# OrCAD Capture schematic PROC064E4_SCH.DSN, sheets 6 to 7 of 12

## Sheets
6 07. RGMII ETHERNET PHY 1: size C; title: RGMII ETHERNET PHY 1
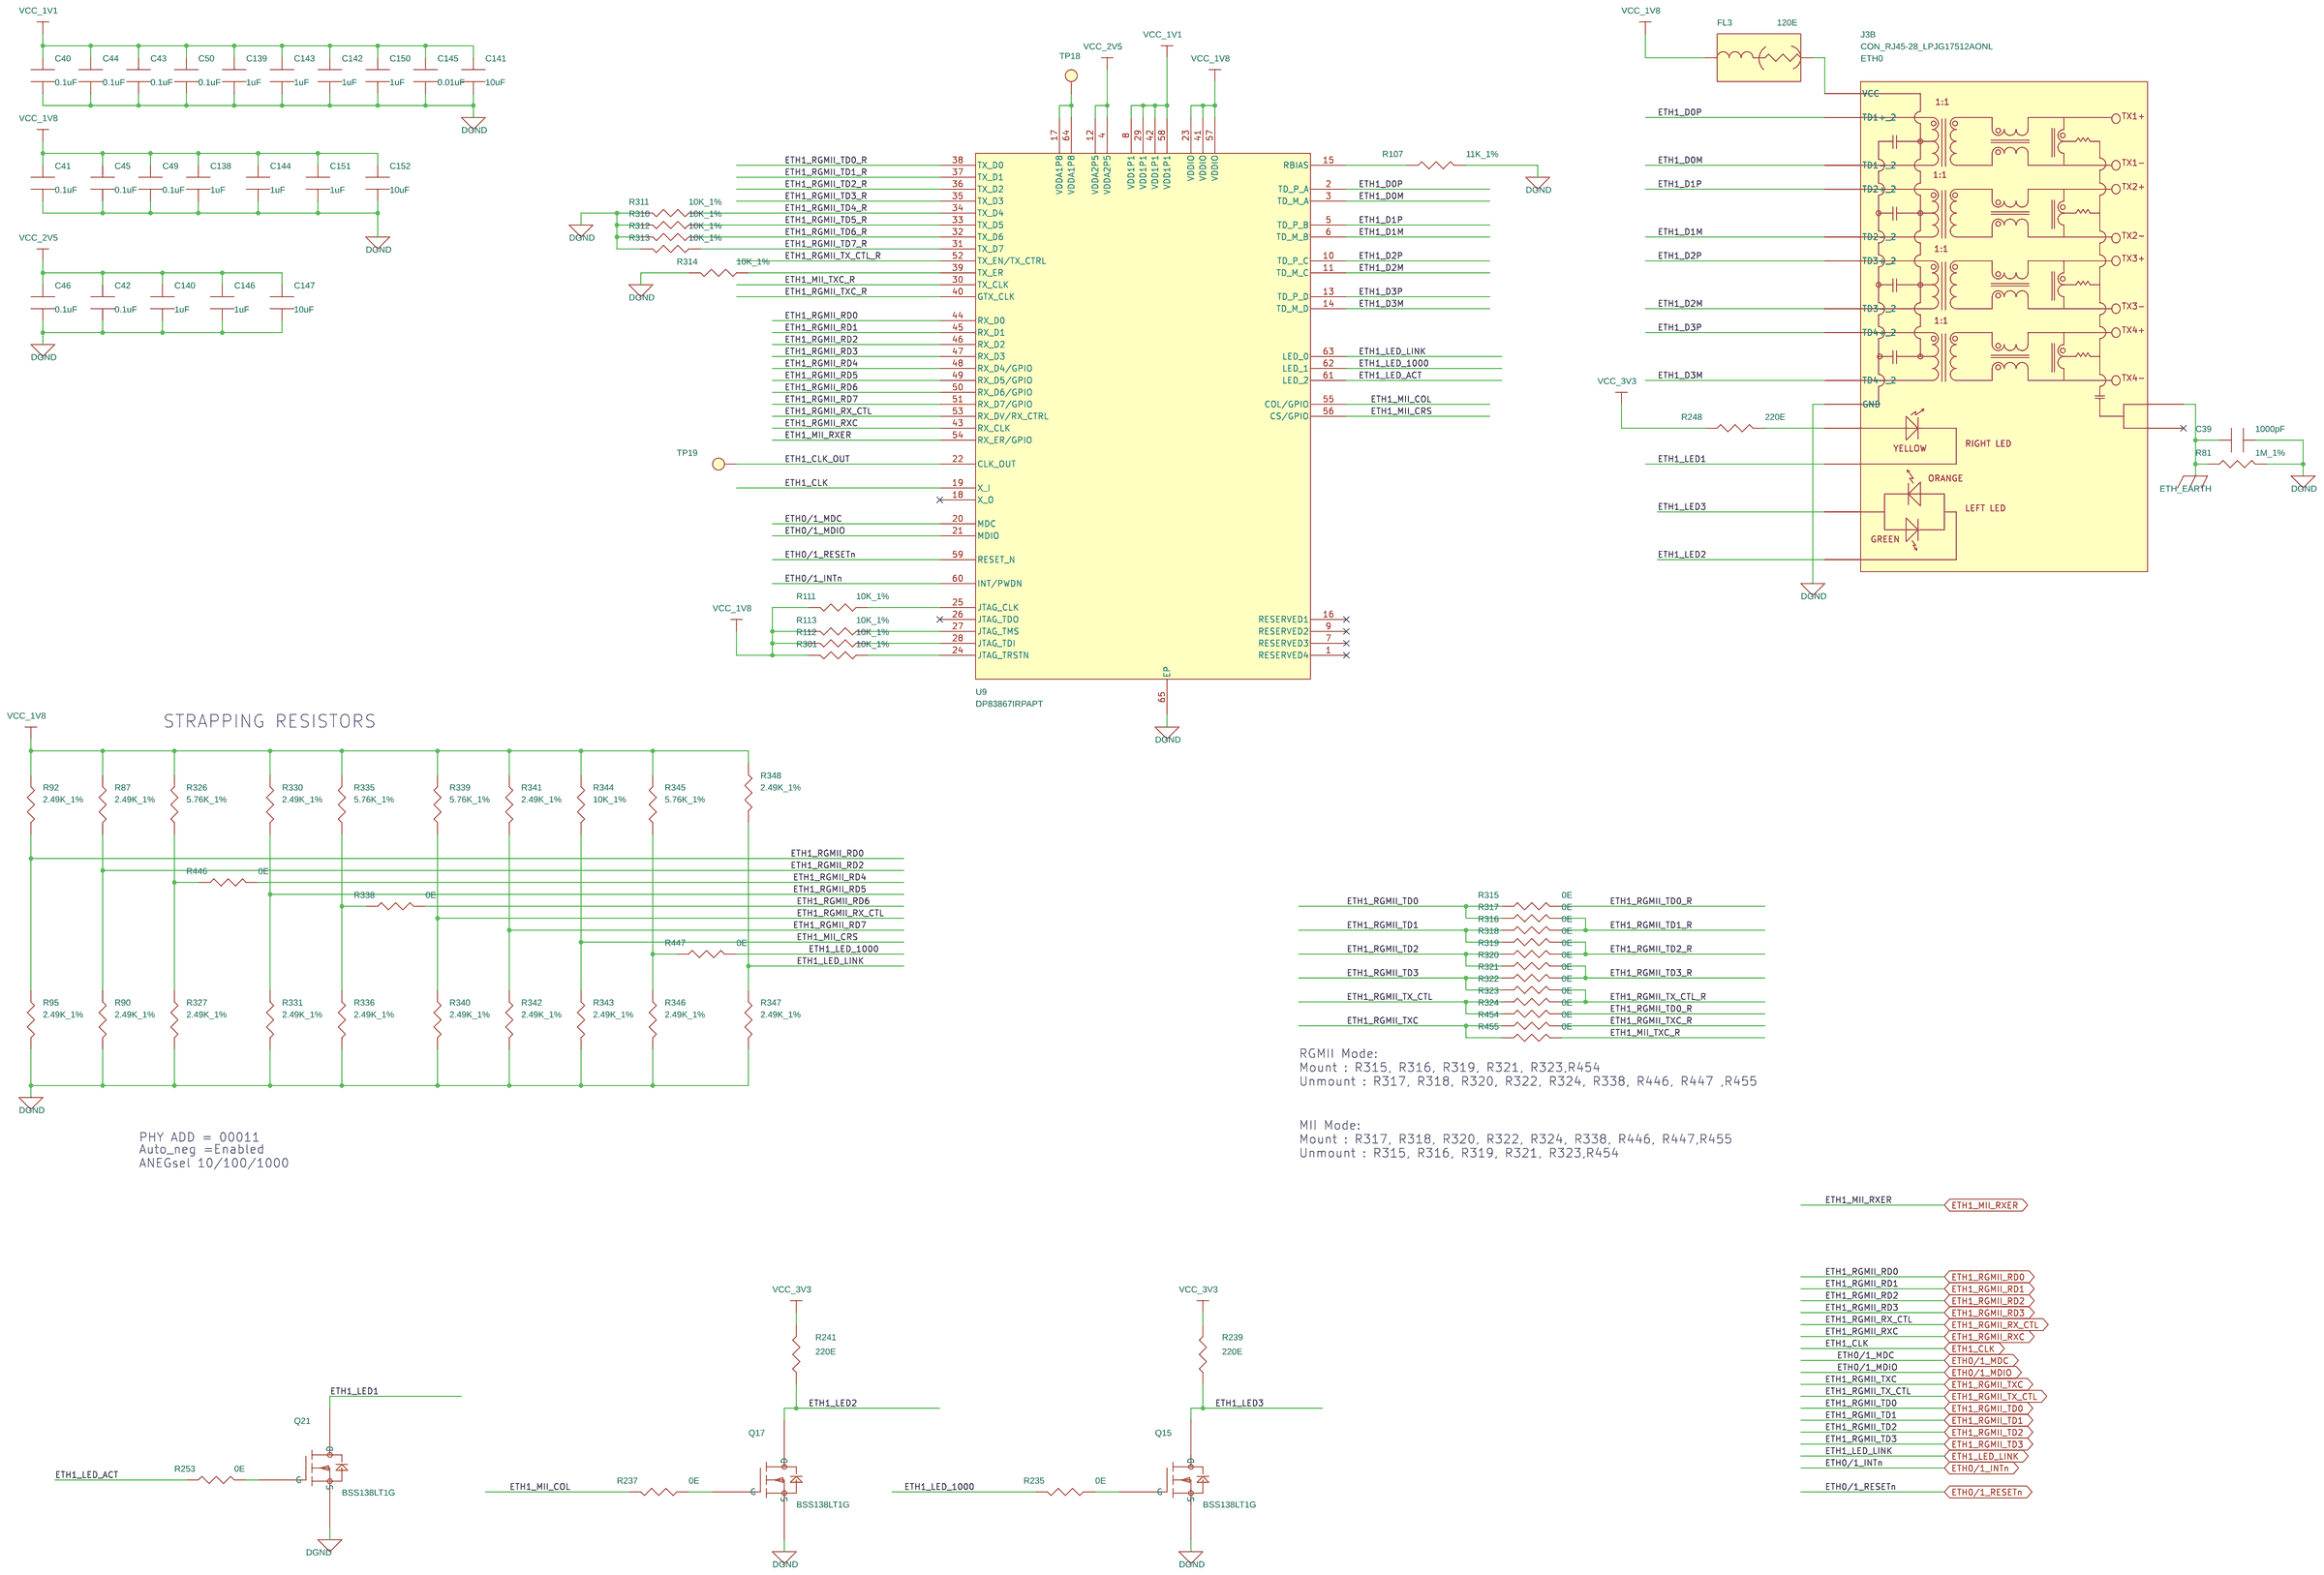
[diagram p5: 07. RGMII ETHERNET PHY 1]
7 08. RGMII ETHERNET PHY 2: size C; title: RGMII ETHERNET PHY 2
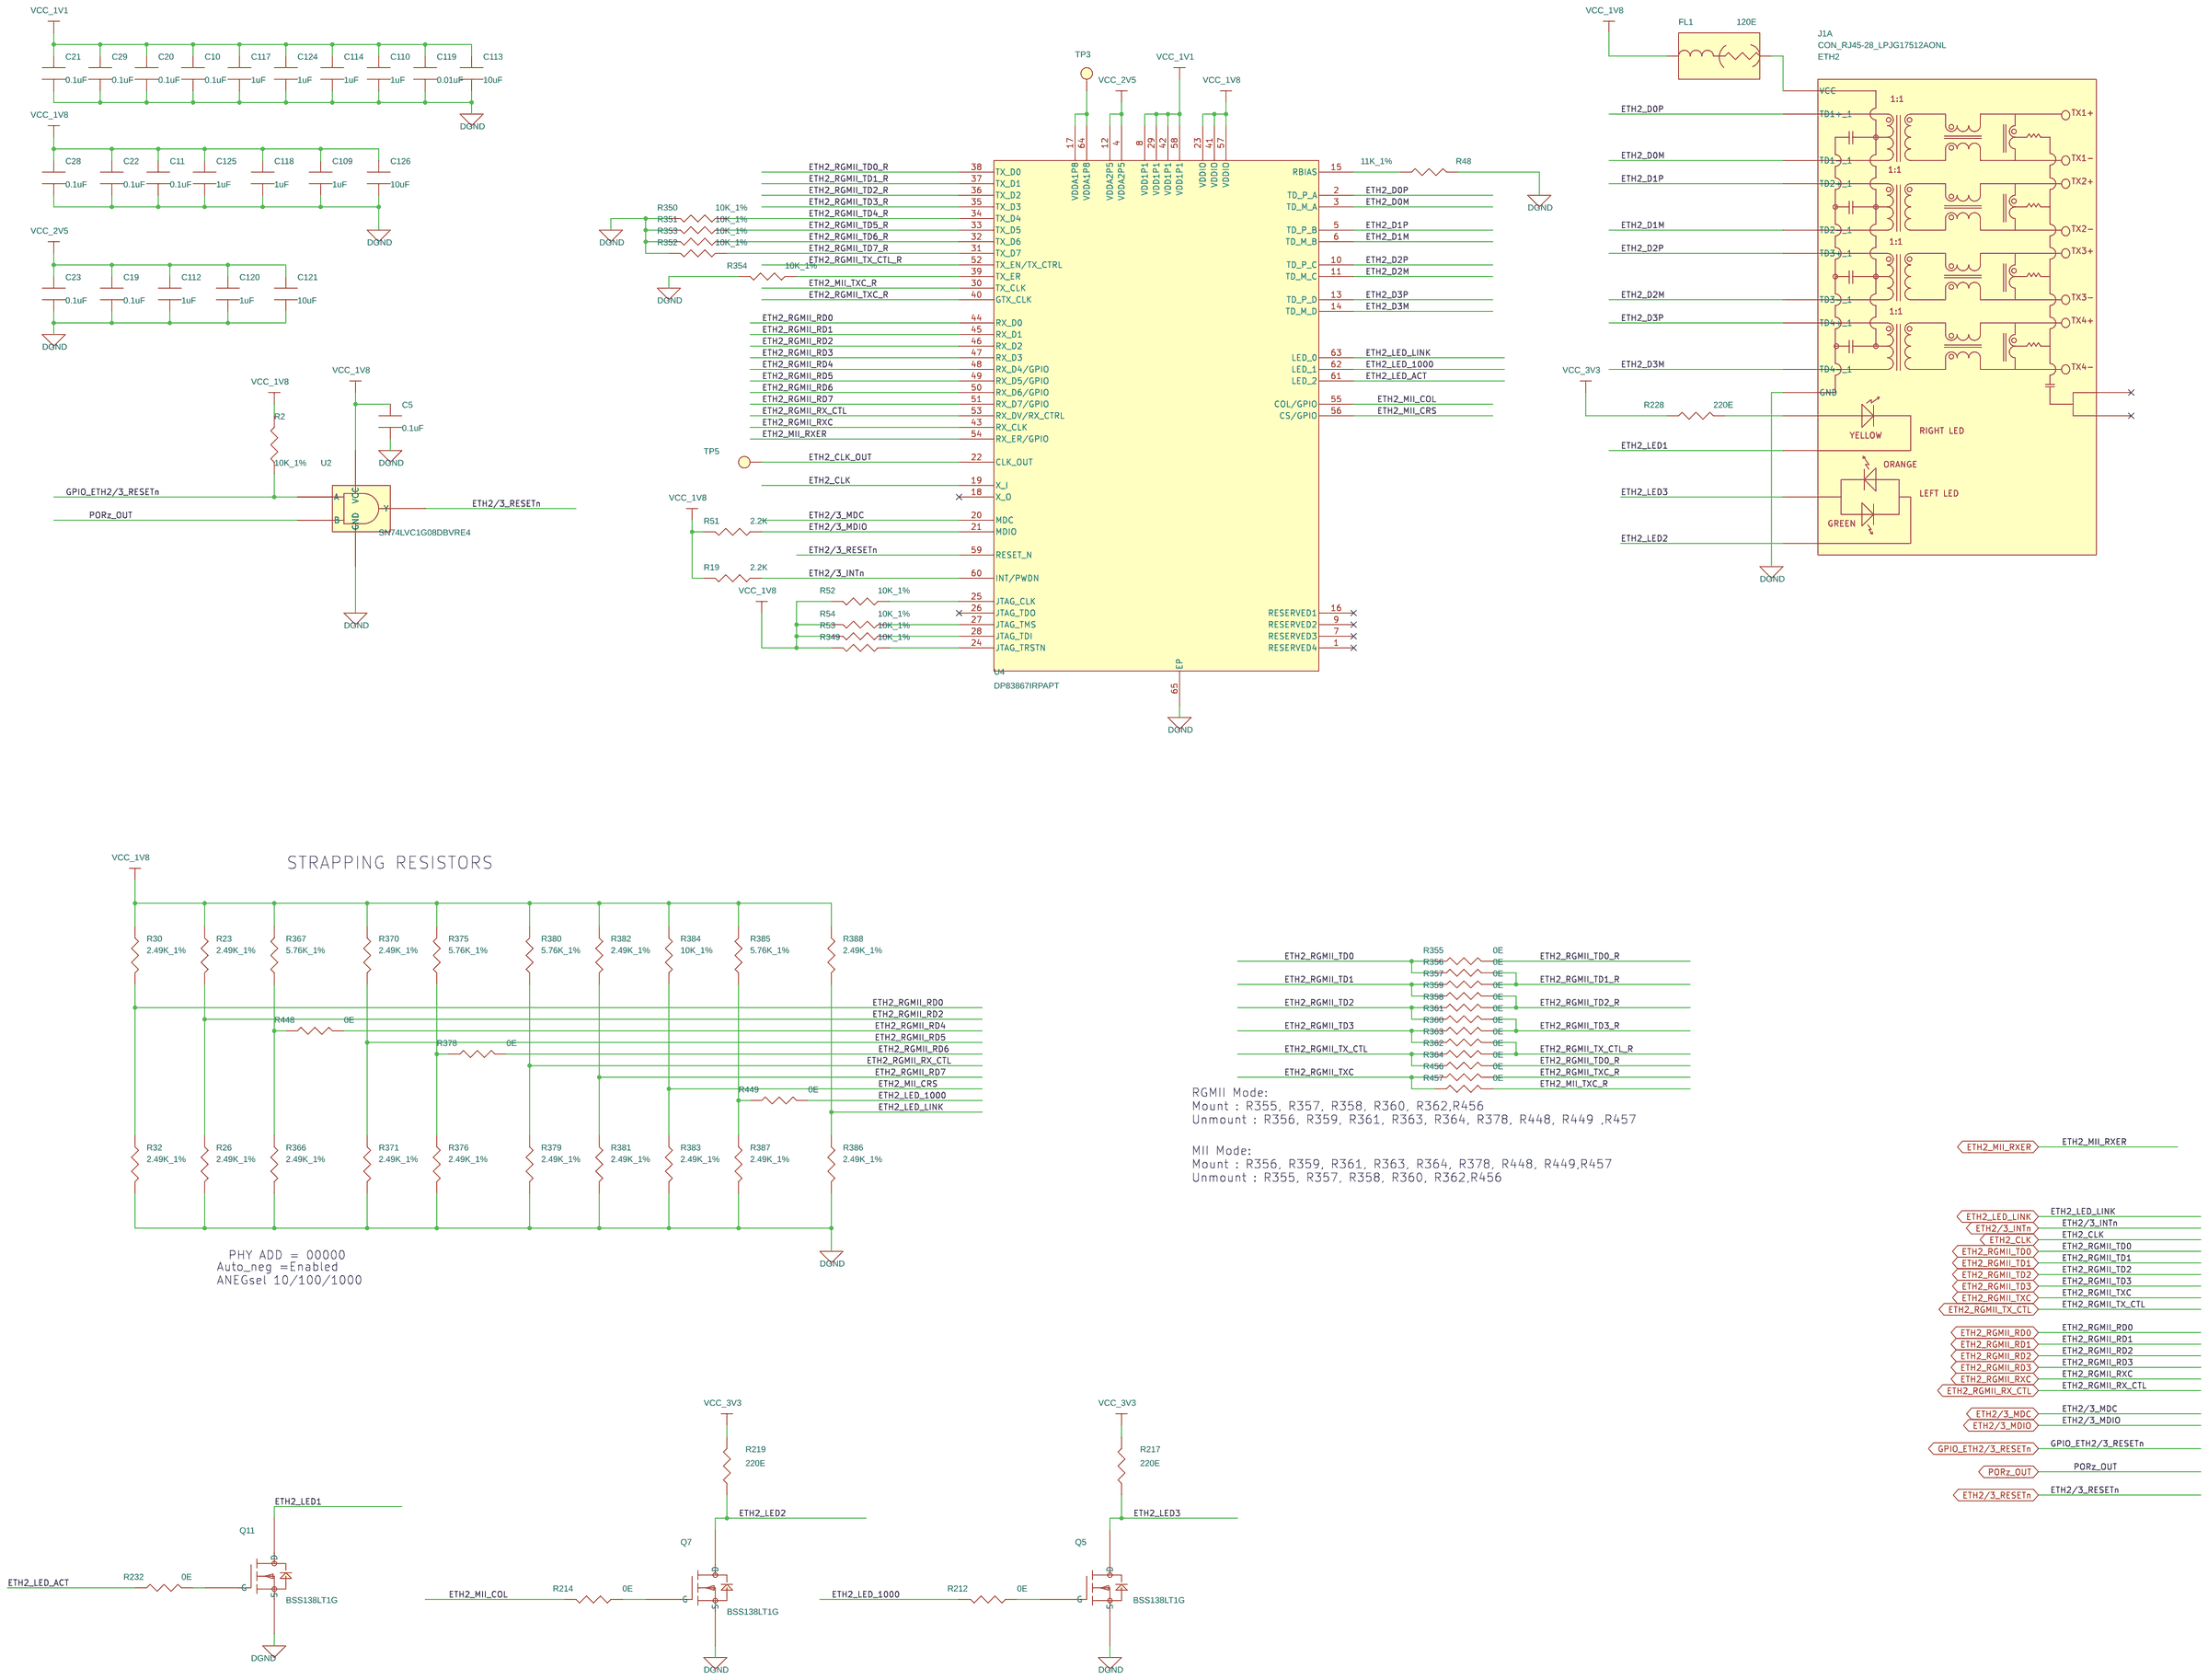
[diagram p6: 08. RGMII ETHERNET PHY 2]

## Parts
sheet 06. RGMII ETHERNET PHY 0
J3  CON_RJ45-28_LPJG17512AONL  [CON_RJ45-28_LPJG17512_S_R_T_25-3]  (sections A,B)
sheet 07. RGMII ETHERNET PHY 1
C39  1000pF  [CAP1206]
C40  0.1uF  [CAP0402_0-75]
C41  0.1uF  [CAP0402_0-75]
C42  0.1uF  [CAP0402_0-75]
C43  0.1uF  [CAP0402_0-75]
C44  0.1uF  [CAP0402_0-75]
C45  0.1uF  [CAP0402_0-75]
C46  0.1uF  [CAP0402_0-75]
C49  0.1uF  [CAP0402_0-75]
C50  0.1uF  [CAP0402_0-75]
C138  1uF  [CAP0402_0-75]
C139  1uF  [CAP0402_0-75]
C140  1uF  [CAP0402_0-75]
C141  10uF  [CAP0603_1]
C142  1uF  [CAP0402_0-75]
C143  1uF  [CAP0402_0-75]
C144  1uF  [CAP0402_0-75]
C145  0.01uF  [CAP0402]
C146  1uF  [CAP0402_0-75]
C147  10uF  [CAP0603_1]
C150  1uF  [CAP0402_0-75]
C151  1uF  [CAP0402_0-75]
C152  10uF  [CAP0603_1]
FL3  120E  [EMIFIL_BLM15A_0402_0-6]
Q15  BSS138LT1G  [SOT23-123]
Q17  BSS138LT1G  [SOT23-123]
Q21  BSS138LT1G  [SOT23-123]
R81  1M_1%  [RES0402]
R87  2.49K_1%  [RES0402]
R90  2.49K_1%  [RES0402]
R92  2.49K_1%  [RES0402]
R95  2.49K_1%  [RES0402]
R107  11K_1%  [RES0402_0-5]
R111  10K_1%  [RES0402_0-5]
R112  10K_1%  [RES0402_0-5]
R113  10K_1%  [RES0402_0-5]
R235  0E  [RES0402_0-5]
R237  0E  [RES0402_0-5]
R239  220E  [RES0402_0-5]
R241  220E  [RES0402_0-5]
R248  220E  [RES0402_0-5]
R253  0E  [RES0402_0-5]
R301  10K_1%  [RES0402_0-5]
R310  10K_1%  [RES0402_0-5]
R311  10K_1%  [RES0402_0-5]
R312  10K_1%  [RES0402_0-5]
R313  10K_1%  [RES0402_0-5]
R314  10K_1%  [RES0402_0-5]
R315  0E  [RES0402_0-5]
R316  0E  [RES0402_0-5]
R317  0E  [RES0402_0-5]
R318  0E  [RES0402_0-5]
R319  0E  [RES0402_0-5]
R320  0E  [RES0402_0-5]
R321  0E  [RES0402_0-5]
R322  0E  [RES0402_0-5]
R323  0E  [RES0402_0-5]
R324  0E  [RES0402_0-5]
R326  5.76K_1%  [RES0402]
R327  2.49K_1%  [RES0402]
R330  2.49K_1%  [RES0402]
R331  2.49K_1%  [RES0402]
R335  5.76K_1%  [RES0402]
R336  2.49K_1%  [RES0402]
R338  0E  [RES0402_0-5]
R339  5.76K_1%  [RES0402]
R340  2.49K_1%  [RES0402]
R341  2.49K_1%  [RES0402]
R342  2.49K_1%  [RES0402]
R343  2.49K_1%  [RES0402]
R344  10K_1%  [RES0402_0-5]
R345  5.76K_1%  [RES0402]
R346  2.49K_1%  [RES0402]
R347  2.49K_1%  [RES0402]
R348  2.49K_1%  [RES0402]
R446  0E  [RES0402_0-5]
R447  0E  [RES0402_0-5]
R454  0E  [RES0402_0-5]
R455  0E  [RES0402_0-5]
TP18  TP40_SMD  [TP40_SMD]
TP19  TP40_SMD  [TP40_SMD]
U9  DP83867IRPAPT  [EQFP64_19-68_400X400]
sheet 08. RGMII ETHERNET PHY 2
C5  0.1uF  [CAP0402_0-75]
C10  0.1uF  [CAP0402_0-75]
C11  0.1uF  [CAP0402_0-75]
C19  0.1uF  [CAP0402_0-75]
C20  0.1uF  [CAP0402_0-75]
C21  0.1uF  [CAP0402_0-75]
C22  0.1uF  [CAP0402_0-75]
C23  0.1uF  [CAP0402_0-75]
C28  0.1uF  [CAP0402_0-75]
C29  0.1uF  [CAP0402_0-75]
C109  1uF  [CAP0402_0-75]
C110  1uF  [CAP0402_0-75]
C112  1uF  [CAP0402_0-75]
C113  10uF  [CAP0603_1]
C114  1uF  [CAP0402_0-75]
C117  1uF  [CAP0402_0-75]
C118  1uF  [CAP0402_0-75]
C119  0.01uF  [CAP0402]
C120  1uF  [CAP0402_0-75]
C121  10uF  [CAP0603_1]
C124  1uF  [CAP0402_0-75]
C125  1uF  [CAP0402_0-75]
C126  10uF  [CAP0603_1]
FL1  120E  [EMIFIL_BLM15A_0402_0-6]
Q5  BSS138LT1G  [SOT23-123]
Q7  BSS138LT1G  [SOT23-123]
Q11  BSS138LT1G  [SOT23-123]
R2  10K_1%  [RES0402_0-5]
R19  2.2K  [RES0402_0-5]
R23  2.49K_1%  [RES0402]
R26  2.49K_1%  [RES0402]
R30  2.49K_1%  [RES0402]
R32  2.49K_1%  [RES0402]
R48  11K_1%  [RES0402_0-5]
R51  2.2K  [RES0402_0-5]
R52  10K_1%  [RES0402_0-5]
R53  10K_1%  [RES0402_0-5]
R54  10K_1%  [RES0402_0-5]
R212  0E  [RES0402_0-5]
R214  0E  [RES0402_0-5]
R217  220E  [RES0402_0-5]
R219  220E  [RES0402_0-5]
R228  220E  [RES0402_0-5]
R232  0E  [RES0402_0-5]
R349  10K_1%  [RES0402_0-5]
R350  10K_1%  [RES0402_0-5]
R351  10K_1%  [RES0402_0-5]
R352  10K_1%  [RES0402_0-5]
R353  10K_1%  [RES0402_0-5]
R354  10K_1%  [RES0402_0-5]
R355  0E  [RES0402_0-5]
R356  0E  [RES0402_0-5]
R357  0E  [RES0402_0-5]
R358  0E  [RES0402_0-5]
R359  0E  [RES0402_0-5]
R360  0E  [RES0402_0-5]
R361  0E  [RES0402_0-5]
R362  0E  [RES0402_0-5]
R363  0E  [RES0402_0-5]
R364  0E  [RES0402_0-5]
R366  2.49K_1%  [RES0402]
R367  5.76K_1%  [RES0402]
R370  2.49K_1%  [RES0402]
R371  2.49K_1%  [RES0402]
R375  5.76K_1%  [RES0402]
R376  2.49K_1%  [RES0402]
R378  0E  [RES0402_0-5]
R379  2.49K_1%  [RES0402]
R380  5.76K_1%  [RES0402]
R381  2.49K_1%  [RES0402]
R382  2.49K_1%  [RES0402]
R383  2.49K_1%  [RES0402]
R384  10K_1%  [RES0402_0-5]
R385  5.76K_1%  [RES0402]
R386  2.49K_1%  [RES0402]
R387  2.49K_1%  [RES0402]
R388  2.49K_1%  [RES0402]
R448  0E  [RES0402_0-5]
R449  0E  [RES0402_0-5]
R456  0E  [RES0402_0-5]
R457  0E  [RES0402_0-5]
TP3  TP40_SMD  [TP40_SMD]
TP5  TP40_SMD  [TP40_SMD]
U2  SN74LVC1G08DBVRE4  [SOT23-5]
U4  DP83867IRPAPT  [EQFP64_19-68_400X400]
sheet 09. RGMII ETHERNET PHY 3
J1  CON_RJ45-28_LPJG17512AONL  [CON_RJ45-28_LPJG17512_S_R_T_25-3]  (sections A,B)

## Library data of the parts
J3 = CON_RJ45-28_LPJG17512AONL: CON JACK RJ45 28POS REGISTERED FEMALE RA TH; Chkd/date: MANIRAJA/010817; Crtd /date: MANIRAJA/010817; Custom_Duty: 24%; Customs_HS_Code: 85369090; Distributor_name: NA; Distributor_part_number: NA; Height: 25.30MM; Mfr_name: LINK-PP; Mfr_part_number: LPJG17512AONL; Mistral Part No: 150017080001-R; Package: THRU-HOLE; Part_type: CONNECTOR\JACK; Project: TI_SVB_DUT; RoHS: RoHS; TEXT2: ETH1; Temperature: 0°C+70°C; Tolerance: NA; Voltage: NA; Wattage: NA; Weight: NA; TEXT1: ETH0; Datasheet: Y:\MIS_DATABASE\DATASHEETS\CONNECTORS\LPJG17512AONL.PDF
C39 = CAP: CAP CERAMIC 1000pF 2KV 10% X7R 1206; Chkd/date: SHREESHAIL/291106; Crtd /date: MAZHAR/281106; Custom_Duty: 15%; Customs_HS_Code: 85322990; Distributor_name: DIGIKEY; Distributor_part_number: 478-2956-1-ND; Footprint Path: Y:\MIS_DATABASE\Library\ALTIUM_TOOL\PCB_FOOTPRINTS\Altium_Footprint_Lib.PcbLib; Height: 1.50MM; Library Path: Y:\MIS_DATABASE\Library\ALTIUM_TOOL\SCHEMATICS_PARTS\MS_DISCRETE_Library.schlib; Mfr_name: AVX CORPORATION; Mfr_part_number: 1206GC102KAT1A; Mistral Part No: 120009030147-R; Package: 1206; Part_type: CAPACITORS\CERAMIC; Project: ADR1B; RoHS: RoHS; Temperature: -55°C+125°C; Tolerance: 10%; Voltage: 2KV; Weight: NA; Datasheet: Y:\MIS_DATABASE\DATASHEETS\CAPACITORS\AVX_MLC.PDF
C5 C10 C11 C19-C23 C28 C29 C40-C46 C49 C50 = CAP: CAP CERAMIC 0.1uF 25V 10% X5R 0402; Chkd/date: MANIRAJA/210817; Crtd /date: MANIRAJA/210817; Custom_Duty: 15%; Customs_HS_Code: 85322990; Distributor_name: DIGIKEY; Distributor_part_number: 490-5920-1-ND; Footprint Path: Y:\MIS_DATABASE\Library\ALTIUM_TOOL\PCB_FOOTPRINTS\Altium_Footprint_Lib.PcbLib; Height: 0.55MM; Library Path: Y:\MIS_DATABASE\Library\ALTIUM_TOOL\SCHEMATICS_PARTS\MS_DISCRETE_Library.schlib; Mfr_name: MURATA; Mfr_part_number: GRM155R61E104KA87D; Mistral Part No: 120017080016-R; Package: 0402; Part_type: CAPACITORS\CERAMIC; Project: TI_RF_DC CARD; RoHS: RoHS; Temperature: -55°C+85°C; Tolerance: 10%; Voltage: 25V; Wattage: NA; Weight: 11mg; Datasheet: Y:\MIS_DATABASE\DATASHEETS\CAPACITORS\GRM188SERIES.PDF
C109 C110 C112 C114 C117 C118 C120 C124 C125 C138-C140 C142-C144 C146 C150 C151 = CAP: CAP CERAMIC 1uF 16V 10% X5R 0402; Chkd/date: MANIRAJA/210817; Crtd /date: MANIRAJA/210817; Custom_Duty: 15%; Customs_HS_Code: 85322990; Distributor_name: DIGIKEY; Distributor_part_number: 587-3709-1-ND; Height: 0.55MM; Mfr_name: TAIYO YUDEN; Mfr_part_number: EMK105BJ105KVHF; Mistral Part No: 120011050002-R; Package: 0402; Part_type: CAPACITORS\CERAMIC; Project: TI_RF_DC CARD; RoHS: RoHS; Temperature: -55°C+85°C; Tolerance: 10%; Voltage: 16V; Wattage: NA; Weight: 0.65mg; Datasheet: Y:\MIS_DATABASE\DATASHEETS\CAPACITORS\EMK105BJ105KVHF.PDF
C113 C121 C126 C141 C147 C152 = CAP: CAP CERAMIC 10uF 25V 20% X5R 0603; Chkd/date: MANIRAJA/130617; Crtd /date: MUDDU/130810; Custom_Duty: 15%; Customs_HS_Code: 85322990; Distributor_name: DIGIKEY; Distributor_part_number: 490-7202-1-ND; Height: 0.90MM; Mfr_name: MURATA; Mfr_part_number: GRM188R61E106MA73D; Mistral Part No: 120010080005-R; Package: 0603; Part_type: CAPACITORS\CERAMIC; Project: PB_BUGBASE; RoHS: RoHS; Temperature: -55°C+85°C; Tolerance: 20%; Voltage: 25V; Wattage: NA; Weight: 6.3mg; Datasheet: Y:\MIS_DATABASE\DATASHEETS\CAPACITORS\MURATA_CMCC.PDF
C119 C145 = CAP: CAP CERAMIC 0.01uF 50V 10% X7R 0402; Alternate_mfr_name_A: MURATA; Alternate_mfr_part_number_A: GRM155R71H103KA88D; Chkd/date: SHREESHAIL/301105; Crtd /date: MAZHAR/040505; Custom_Duty: 15%; Customs_HS_Code: 85322990; Distributor_name: DIGIKEY; Distributor_name_A: DIGIKEY; Distributor_part_number: 399-3066-1-ND; Distributor_part_number_A: 490-4516-1-ND; Height: 0.55MM; Mfr_name: KEMET; Mfr_part_number: C0402C103K5RACTU; Mistral Part No: 120009030025-R; Package: 0402; Part_type: CAPACITORS\CERAMIC; Project: G4_SVGA; RoHS: RoHS; Tolerance: 10%; Voltage: 50V; Datasheet: Y:\MIS_DATABASE\DATASHEETS\CAPACITORS\KEMET-C08.PDF
FL1 FL3 = EMIFILTER_IND: FERRITE CHIP 120E 1.3A 0402; Chkd/date: VASANTHA/010117; Crtd /date: CHAITHANYA/150312; Custom_Duty: 24%; Customs_HS_Code: 85437099; Distributor_name: DIGIKEY; Distributor_part_number: 490-5203-1-ND; Footprint Path: Y:\MIS_DATABASE\Library\ALTIUM_TOOL\PCB_FOOTPRINTS\Altium_Footprint_Lib.PcbLib; Height: 0.55MM; Library Path: Y:\MIS_DATABASE\Library\ALTIUM_TOOL\SCHEMATICS_PARTS\MS_FILTER_Library.schlib; Mfr_name: MURATA; Mfr_part_number: BLM15PD121SN1; Mistral Part No: 130012030043-R; Package: 0402; Part_type: MISC\FILTER; Project: GEN_3-8; RoHS: RoHS; Temperature: -55°C+125°C; Tolerance: 25%; Voltage: NA; Wattage: NA; Weight: 0.65mg; Datasheet: Y:\MIS_DATABASE\DATASHEETS\DISCRETES\INDUCTORS\BLM18K-SERIES.PDF
Q5 Q7 Q11 Q15 Q17 Q21 = MOSFET_BSS138LT1G: IC MOSFET N-CHANNEL 50V, SOT23-3; Chkd/date: VASANTHA/150416; Crtd /date: JEBRAN/060416; Custom_Duty: 15%; Customs_HS_Code: 85423100; Distributor_name: MOUSER; Distributor_part_number: 863-BSS138LT1G; Height: 1.11MM; Mfr_name: ON SEMICONDUCTOR; Mistral Part No: 142016040001-R; Package: SOT23-3; Part_type: ICS\POWER\MOSFET; Project: LRDE_ABCM; RoHS: RoHS; Temperature: -55°C+150°C; Tolerance: NA; Voltage: 50V; Wattage: NA; Weight: NA; Datasheet: Y:\MIS_DATABASE\DATASHEETS\DISCRETES\TRANSISTORS_FETS\BSS138LT1G.PDF
R81 = RESISTOR: RES 1M 1/16W 1% 0402; Chkd/date: VASANTHA/200614; Crtd /date: NAVEED/170614; Custom_Duty: 15%; Customs_HS_Code: 85332119; Distributor_name: DIGIKEY; Distributor_part_number: RMCF0402FT1M00CT-ND; Footprint Path: Y:\MIS_DATABASE\Library\ALTIUM_TOOL\PCB_FOOTPRINTS\Altium_Footprint_Lib.PcbLib; Height: 0.40MM; Library Path: Y:\MIS_DATABASE\Library\ALTIUM_TOOL\SCHEMATICS_PARTS\MS_DISCRETE_Library.schlib; Mfr_name: STACKPOLE ELECTRONICS; Mfr_part_number: RMCF0402FT1M00; Mistral Part No: 110014060045-R; Package: 0402; Part_type: RESISTORS\FIXED; Project: AEGIS_POM; RoHS: RoHS; Temperature: -55°C+155°C; Tolerance: 1%; Voltage: NA; Wattage: 1/16W; Weight: 0.57mg; Datasheet: Y:\MIS_DATABASE\DATASHEETS\RESISTORS\RMCF-SERIES1.PDF
R23 R26 R30 R32 R87 R90 R92 R95 R327 R330 R331 R336 R340-R343 R346-R348 R366 R370 R371 R376 R379 R381-R383 R386-R388 = RESISTOR: RES 2.49K 1/16W 1% 0402; Chkd/date: VASANTHA/270516; Crtd /date: VASANTHA/270516; Custom_Duty: 15%; Customs_HS_Code: 85332119; Distributor_name: DIGIKEY; Distributor_part_number: 311-2.49KLRCT-ND; Height: 0.40MM; Mfr_name: YAGEO AMERICA; Mfr_part_number: RC0402FR-072K49L; Mistral Part No: 110016050020-R; Package: 0402; Part_type: RESISTORS\FIXED; Project: TMDXCSKCC; RoHS: RoHS; Temperature: -55°C+155°C; Tolerance: 1%; Voltage: NA; Wattage: 1/16W; Weight: NA; Datasheet: Y:\MIS_DATABASE\DATASHEETS\RESISTORS\RC0402FR.PDF
R48 R107 = RESISTOR: RES 11K 1/16W 1% 0402; Chkd/date: VASANTHA/251115; Crtd /date: VASANTHA/251115; Custom_Duty: 15%; Customs_HS_Code: 85332119; Distributor_name: DIGIKEY; Distributor_part_number: 311-11.0KLRCT-ND; Height: 0.40MM; Mfr_name: YAGEO AMERICA; Mfr_part_number: RC0402FR-0711KL; Mistral Part No: 110015110012-P; Package: 0402; Part_type: RESISTORS\FIXED; Project: TI_VLAN_SWITCH; RoHS: Pb-Free; Temperature: -55°C+155°C; Tolerance: 1%; Voltage: NA; Wattage: 1/16W; Weight: 0.65mg; Datasheet: Y:\MIS_DATABASE\DATASHEETS\RESISTORS\YAGEO-RC0402.PDF
R2 R52-R54 R111-R113 R301 R310-R314 R344 R349-R354 R384 = RESISTOR: RES 10K 1/16W 1% 0402; Chkd/date: VASANTHA/201216; Crtd /date: GEETHA/290506; Custom_Duty: 15%; Customs_HS_Code: 85332119; Distributor_name: DIGIKEY; Distributor_part_number: 311-10.0KLRTR-ND; Footprint Path: Y:\MIS_DATABASE\Library\ALTIUM_TOOL\PCB_FOOTPRINTS\Altium_Footprint_Lib.PcbLib; Height: 0.40MM; Library Path: Y:\MIS_DATABASE\Library\ALTIUM_TOOL\SCHEMATICS_PARTS\MS_DISCRETE_Library.schlib; Mfr_name: YAGEO AMERICA; Mfr_part_number: RC0402FR-0710KL; Mistral Part No: 110009030220-P; Package: 0402; Part_type: RESISTORS\FIXED; Project: VOCERA; RoHS: Pb-Free; Temperature: -55°C+155°C; Tolerance: 1%; Voltage: NA; Wattage: 1/16W; Weight: 0.65mg; Datasheet: Y:\MIS_DATABASE\DATASHEETS\RESISTORS\YAGEO-RC0402.PDF
R212 R214 R232 R235 R237 R253 R315-R324 R338 R355-R364 R378 R446-R449 R454-R457 = RESISTOR: RES 0E 1/16W 0402; Chkd/date: VASANTHA/201216; Crtd /date: MUDDU/190810; Custom_Duty: 15%; Customs_HS_Code: 85332119; Distributor_name: DIGIKEY; Distributor_part_number: 541-0.0JCT-ND; Footprint Path: Y:\MIS_DATABASE\Library\ALTIUM_TOOL\PCB_FOOTPRINTS\Altium_Footprint_Lib.PcbLib; Height: 0.40MM; Library Path: Y:\MIS_DATABASE\Library\ALTIUM_TOOL\SCHEMATICS_PARTS\MS_DISCRETE_Library.schlib; Mfr_name: VISHAY; Mfr_part_number: CRCW04020000Z0ED; Mistral Part No: 110010080019-P; Package: 0402; Part_type: RESISTORS\FIXED; Project: PB_BUGBASE; RoHS: Pb-Free; Temperature: -55°C+155°C; Tolerance: NA; Voltage: NA; Wattage: 1/16W; Weight: 0.65g/1000pcs; Datasheet: Y:\MIS_DATABASE\DATASHEETS\RESISTORS\CRCW0603.PDF
R217 R219 R228 R239 R241 R248 = RESISTOR: RES 220E 1/16W 5% 0402; Chkd/date: VASANTHA/291216; Crtd /date: GEETHA/260406; Custom_Duty: 15%; Customs_HS_Code: 85332119; Distributor_name: DIGIKEY; Distributor_part_number: P220JCT-ND; Footprint Path: Y:\MIS_DATABASE\Library\ALTIUM_TOOL\PCB_FOOTPRINTS\Altium_Footprint_Lib.PcbLib; Height: 0.40MM; Library Path: Y:\MIS_DATABASE\Library\ALTIUM_TOOL\SCHEMATICS_PARTS\MS_DISCRETE_Library.schlib; Mfr_name: PANASONIC-ECG; Mfr_part_number: ERJ-2GEJ221X; Mistral Part No: 110009030506-R; Package: 0402; Part_type: RESISTORS\FIXED; Project: RED EYE; RoHS: RoHS; Temperature: -55°C+155°C; Tolerance: 5%; Voltage: NA; Wattage: 1/16W; Weight: 0.8g/1000pcs; Datasheet: Y:\MIS_DATABASE\DATASHEETS\RESISTORS\ERJ12.PDF
R326 R335 R339 R345 R367 R375 R380 R385 = RESISTOR: RES 5.76K 1/10W 1% 0402; Chkd/date: MAZHAR/150709; Crtd /date: USMAN/220808; Custom_Duty: 15%; Customs_HS_Code: 85332119; Distributor_name: DIGIKEY; Distributor_part_number: P5.76KLCT-ND; Footprint Path: Y:\MIS_DATABASE\Library\ALTIUM_TOOL\PCB_FOOTPRINTS\Altium_Footprint_Lib.PcbLib; Height: 0.40MM; Library Path: Y:\MIS_DATABASE\Library\ALTIUM_TOOL\SCHEMATICS_PARTS\MS_DISCRETE_Library.schlib; Mfr_name: PANASONIC-ECG; Mfr_part_number: ERJ-2RKF5761X; Mistral Part No: 110009030945-R; Package: 0402; Part_type: RESISTORS\FIXED; Project: CPB; RoHS: RoHS; Tolerance: 1%; Wattage: 1/10W; Datasheet: Y:\MIS_DATABASE\DATASHEETS\RESISTORS\PAN-ERJSERIES.PDF
TP3 TP5 TP18 TP19 = TESTPOINT: TESTPOINT CIR 40 SMD; Chkd/date: MAZHAR/190505; Crtd /date: MAZHAR/190505; Distributor_name: NA; Distributor_part_number: NA; Footprint Path: Y:\MIS_DATABASE\Library\ALTIUM_TOOL\PCB_FOOTPRINTS\Altium_Footprint_Lib.PcbLib; Height: NA; Library Path: Y:\MIS_DATABASE\Library\ALTIUM_TOOL\SCHEMATICS_PARTS\MS_DISCRETE_Library.schlib; MECHANICAL 3D STEP FILE: NA; Mfr_name: LOCAL; Mistral Part No: 130009030933; Package: SMD; Project: RAINIER-3; RoHS: NA; Temperature: NA; Tolerance: NA; Voltage: NA; Wattage: NA; Weight: NA; Datasheet: NA
U4 U9 = DP83867IRPAPT_HTQFP64: IC HIGH IMMUNITY 10/100/1000 Mb/s ETHERNET PHY LAYER TRANSCEIVER HTQFP64; Chkd/date: VASANTHA/250516; Crtd /date: VASANTHA/250516; Custom_Duty: 15%; Customs_HS_Code: 85423100; Distributor_name: DIGIKEY; Distributor_part_number: 296-41117-1-ND; Height: 1.20MM; Mfr_name: TEXAS INSTRUMENTS; Mistral Part No: 143016050002-R; Package: HTQFP64; Part_type: ICS\TELECOM\TRANSCEIVER; Project: TMDXCSKCC; RoHS: RoHS; Temperature: -40°C+85°C; Tolerance: NA; Voltage: NA; Wattage: NA; Weight: NA; Datasheet: Y:\MIS_DATABASE\DATASHEETS\ICS\DIGITAL\BUSTRANSCEIVER\DP83867I.PDF
R19 R51 = RESISTOR: RES 2.2K 1/16W 5% 0402; Chkd/date: VASANTHA/061216; Crtd /date: BAVISH/021210; Custom_Duty: 15%; Customs_HS_Code: 85332119; Distributor_name: DIGIKEY; Distributor_part_number: 311-2.2KJRCT-ND; Footprint Path: VALUE IS VAILABLE 3 TIMES; Height: 0.40MM; Mfr_name: YAGEO AMERICA; Mfr_part_number: RC0402JR-072K2L; Mistral Part No: 110010120018-R; Package: 0402; Part_type: RESISTORS\FIXED; Project: TE4; RoHS: RoHS; Temperature: -55°C+155°C; Tolerance: 5%; Voltage: NA; Wattage: 1/16W; Weight: 0.65mg; Datasheet: Y:\MIS_DATABASE\DATASHEETS\RESISTORS\YAGEO.PDF
U2 = SN74LVC1G08DBVRE4_SOT23-5: IC SINGLE 2-INPUT POSITIVE AND GATE SOT23-5; Chkd/date: SUHAS/221010; Crtd /date: USMAN/151008; Custom_Duty: 15%; Customs_HS_Code: 85423100; Distributor_name: DIGIKEY; Distributor_part_number: SN74LVC1G08DBVRE4-ND; Height: 1.45MM; Mfr_name: TEXAS INSTRUMENTS; Mistral Part No: 141009060026-R; Part_type: ICS\DIGITAL\GATES; Project: KHAN_MAIN; RoHS: Sb/ Br FREE; Temperature: -40°C+85°C; Datasheet: Y:\MIS_DATABASE\DATASHEETS\ICS\DIGITAL\GATES\SN74LVC1G08.PDF
J1 = CON_RJ45-28_LPJG17512AONL: CON JACK RJ45 28POS REGISTERED FEMALE RA TH; Chkd/date: MANIRAJA/010817; Crtd /date: MANIRAJA/010817; Custom_Duty: 24%; Customs_HS_Code: 85369090; Distributor_name: NA; Distributor_part_number: NA; Height: 25.30MM; Mfr_name: LINK-PP; Mfr_part_number: LPJG17512AONL; Mistral Part No: 150017080001-R; Package: THRU-HOLE; Part_type: CONNECTOR\JACK; Project: TI_SVB_DUT; RoHS: RoHS; TEXT1: ETH2; Temperature: 0°C+70°C; Tolerance: NA; Voltage: NA; Wattage: NA; Weight: NA; Datasheet: Y:\MIS_DATABASE\DATASHEETS\CONNECTORS\LPJG17512AONL.PDF

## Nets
DGND: C5.2 C10.2 C11.2 C19.2 C20.2 C21.2 C22.2 C23.2 C28.2 C29.2 C39.2 C40.2 C41.2 C42.2 C43.2 C44.2 C45.2 C46.2 C49.2 C50.2 C109.2 C110.2 C112.2 C113.2 C114.2 C117.2 C118.2 C119.2 C120.2 C121.2 C124.2 C125.2 C126.2 C138.2 C139.2 C140.2 C141.2 C142.2 C143.2 C144.2 C145.2 C146.2 C147.2 C150.2 C151.2 C152.2 J1.A10(GND) J3.B10(GND) Q5.2(S) Q7.2(S) Q11.2(S) Q15.2(S) Q17.2(S) Q21.2(S) R26.2 R32.2 R48.1 R81.2 R90.2 R95.2 R107.1 R310.2 R311.2 R312.2 R313.2 R314.2 R327.2 R331.2 R336.2 R340.2 R342.2 R343.2 R346.2 R347.2 R350.2 R351.2 R352.2 R353.2 R354.2 R366.2 R371.2 R376.2 R379.2 R381.2 R383.2 R386.2 R387.2 U2.3(GND) U4.65(EP) U9.65(EP) ; also on sheet 4 5 8 9 11 12
VCC_1V1: C10.1 C20.1 C21.1 C29.1 C40.1 C43.1 C44.1 C50.1 C110.1 C113.1 C114.1 C117.1 C119.1 C124.1 C139.1 C141.1 C142.1 C143.1 C145.1 C150.1 U4.8(VDD1P1) U4.29(VDD1P1) U4.42(VDD1P1) U4.58(VDD1P1) U9.8(VDD1P1) U9.29(VDD1P1) U9.42(VDD1P1) U9.58(VDD1P1) ; also on sheet 4 5 8
VCC_1V8: C5.1 C11.1 C22.1 C28.1 C41.1 C45.1 C49.1 C109.1 C118.1 C125.1 C126.1 C138.1 C144.1 C151.1 C152.1 FL1.1 FL3.1 R2.2 R19.2 R23.1 R30.1 R51.2 R52.2 R53.2 R54.2 R87.1 R92.1 R111.2 R112.2 R113.2 R301.2 R326.2 R330.1 R335.2 R339.2 R341.1 R344.1 R345.2 R348.1 R349.2 R367.2 R370.1 R375.2 R380.2 R382.1 R384.1 R385.2 R388.1 U2.5(VCC) U4.23(VDDIO) U4.41(VDDIO) U4.57(VDDIO) U9.23(VDDIO) U9.41(VDDIO) U9.57(VDDIO) ; also on sheet 4 5 8 11 12
VCC_2V5: C19.1 C23.1 C42.1 C46.1 C112.1 C120.1 C121.1 C140.1 C146.1 C147.1 U4.4(VDDA2P5) U4.12(VDDA2P5) U9.4(VDDA2P5) U9.12(VDDA2P5) ; also on sheet 4 5 8
VCC_3V3: R217.2 R219.2 R228.1 R239.2 R241.2 R248.1 ; also on sheet 4 5 8 9 11 12
ETH0/1_INTn: U9.60(INT/PWDN) ; also on sheet 4 5
ETH0/1_MDC: U9.20(MDC) ; also on sheet 4 5
ETH0/1_MDIO: U9.21(MDIO) ; also on sheet 4 5
ETH0/1_RESETn: U9.59(RESET_N) ; also on sheet 5
ETH1_CLK: U9.19(X_I) ; also on sheet 4
ETH1_CLK_OUT: TP19.1(TP) U9.22(CLK_OUT)
ETH1_D0M: J3.B2(TD1-_2) U9.3(TD_M_A)
ETH1_D0P: J3.B1(TD1+_2) U9.2(TD_P_A)
ETH1_D1M: J3.B4(TD2-_2) U9.6(TD_M_B)
ETH1_D1P: J3.B3(TD2+_2) U9.5(TD_P_B)
ETH1_D2M: J3.B6(TD3-_2) U9.11(TD_M_C)
ETH1_D2P: J3.B5(TD3+_2) U9.10(TD_P_C)
ETH1_D3M: J3.B8(TD4-_2) U9.14(TD_M_D)
ETH1_D3P: J3.B7(TD4+_2) U9.13(TD_P_D)
ETH1_LED1: J3.B11 Q21.3(D)
ETH1_LED2: J3.B13 Q17.3(D) R241.1
ETH1_LED3: J3.B14 Q15.3(D) R239.1
ETH1_LED_1000: R235.2 R447.2 U9.62(LED_1)
ETH1_LED_ACT: R253.1 U9.61(LED_2)
ETH1_LED_LINK: R347.1 R348.2 U9.63(LED_0) ; also on sheet 4
ETH1_MII_COL: R237.2 U9.55(COL/GPIO)
ETH1_MII_CRS: R343.1 R344.2 U9.56(CS/GPIO)
ETH1_MII_RXER: U9.54(RX_ER/GPIO) ; also on sheet 4
ETH1_MII_TXC_R: R455.2 U9.30(TX_CLK)
ETH1_RGMII_RD0: R92.2 R95.1 U9.44(RX_D0) ; also on sheet 4
ETH1_RGMII_RD1: U9.45(RX_D1) ; also on sheet 4
ETH1_RGMII_RD2: R87.2 R90.1 U9.46(RX_D2) ; also on sheet 4
ETH1_RGMII_RD3: U9.47(RX_D3) ; also on sheet 4
ETH1_RGMII_RD4: R446.2 U9.48(RX_D4/GPIO)
ETH1_RGMII_RD5: R330.2 R331.1 U9.49(RX_D5/GPIO)
ETH1_RGMII_RD6: R338.2 U9.50(RX_D6/GPIO)
ETH1_RGMII_RD7: R341.2 R342.1 U9.51(RX_D7/GPIO)
ETH1_RGMII_RX_CTL: R339.1 R340.1 U9.53(RX_DV/RX_CTRL) ; also on sheet 4
ETH1_RGMII_RXC: U9.43(RX_CLK) ; also on sheet 4
ETH1_RGMII_TD0: R315.1 R317.1 ; also on sheet 4
ETH1_RGMII_TD0_R: R315.2 R324.2 U9.38(TX_D0)
ETH1_RGMII_TD1: R316.1 R318.1 ; also on sheet 4
ETH1_RGMII_TD1_R: R316.2 R317.2 U9.37(TX_D1)
ETH1_RGMII_TD2: R319.1 R320.1 ; also on sheet 4
ETH1_RGMII_TD2_R: R318.2 R319.2 U9.36(TX_D2)
ETH1_RGMII_TD3: R321.1 R322.1 ; also on sheet 4
ETH1_RGMII_TD3_R: R320.2 R321.2 U9.35(TX_D3)
ETH1_RGMII_TD4_R: R311.1 U9.34(TX_D4)
ETH1_RGMII_TD5_R: R310.1 U9.33(TX_D5)
ETH1_RGMII_TD6_R: R312.1 U9.32(TX_D6)
ETH1_RGMII_TD7_R: R313.1 U9.31(TX_D7)
ETH1_RGMII_TX_CTL: R323.1 R324.1 ; also on sheet 4
ETH1_RGMII_TX_CTL_R: R322.2 R323.2 U9.52(TX_EN/TX_CTRL)
ETH1_RGMII_TXC: R454.1 R455.1 ; also on sheet 4
ETH1_RGMII_TXC_R: R454.2 U9.40(GTX_CLK)
ETH2/3_INTn: R19.1 U4.60(INT/PWDN) ; also on sheet 4 8
ETH2/3_MDC: U4.20(MDC) ; also on sheet 4 8
ETH2/3_MDIO: R51.1 U4.21(MDIO) ; also on sheet 4 8
ETH2/3_RESETn: U2.4(Y) U4.59(RESET_N) ; also on sheet 8
ETH2_CLK: U4.19(X_I) ; also on sheet 4
ETH2_CLK_OUT: TP5.1(TP) U4.22(CLK_OUT)
ETH2_D0M: J1.A2(TD1-_1) U4.3(TD_M_A)
ETH2_D0P: J1.A1(TD1+_1) U4.2(TD_P_A)
ETH2_D1M: J1.A4(TD2-_1) U4.6(TD_M_B)
ETH2_D1P: J1.A3(TD2+_1) U4.5(TD_P_B)
ETH2_D2M: J1.A6(TD3-_1) U4.11(TD_M_C)
ETH2_D2P: J1.A5(TD3+_1) U4.10(TD_P_C)
ETH2_D3M: J1.A8(TD4-_1) U4.14(TD_M_D)
ETH2_D3P: J1.A7(TD4+_1) U4.13(TD_P_D)
ETH2_LED1: J1.A11 Q11.3(D)
ETH2_LED2: J1.A13 Q7.3(D) R219.1
ETH2_LED3: J1.A14 Q5.3(D) R217.1
ETH2_LED_1000: R212.2 R449.2 U4.62(LED_1)
ETH2_LED_ACT: R232.1 U4.61(LED_2)
ETH2_LED_LINK: R386.1 R388.2 U4.63(LED_0) ; also on sheet 4
ETH2_MII_COL: R214.2 U4.55(COL/GPIO)
ETH2_MII_CRS: R383.1 R384.2 U4.56(CS/GPIO)
ETH2_MII_RXER: U4.54(RX_ER/GPIO) ; also on sheet 4
ETH2_MII_TXC_R: R457.2 U4.30(TX_CLK)
ETH2_RGMII_RD0: R30.2 R32.1 U4.44(RX_D0) ; also on sheet 4
ETH2_RGMII_RD1: U4.45(RX_D1) ; also on sheet 4
ETH2_RGMII_RD2: R23.2 R26.1 U4.46(RX_D2) ; also on sheet 4
ETH2_RGMII_RD3: U4.47(RX_D3) ; also on sheet 4
ETH2_RGMII_RD4: R448.2 U4.48(RX_D4/GPIO)
ETH2_RGMII_RD5: R370.2 R371.1 U4.49(RX_D5/GPIO)
ETH2_RGMII_RD6: R378.2 U4.50(RX_D6/GPIO)
ETH2_RGMII_RD7: R381.1 R382.2 U4.51(RX_D7/GPIO)
ETH2_RGMII_RX_CTL: R379.1 R380.1 U4.53(RX_DV/RX_CTRL) ; also on sheet 4
ETH2_RGMII_RXC: U4.43(RX_CLK) ; also on sheet 4
ETH2_RGMII_TD0: R355.1 R356.1 ; also on sheet 4
ETH2_RGMII_TD0_R: R355.2 R364.2 U4.38(TX_D0)
ETH2_RGMII_TD1: R357.1 R359.1 ; also on sheet 4
ETH2_RGMII_TD1_R: R356.2 R357.2 U4.37(TX_D1)
ETH2_RGMII_TD2: R358.1 R361.1 ; also on sheet 4
ETH2_RGMII_TD2_R: R358.2 R359.2 U4.36(TX_D2)
ETH2_RGMII_TD3: R360.1 R363.1 ; also on sheet 4
ETH2_RGMII_TD3_R: R360.2 R361.2 U4.35(TX_D3)
ETH2_RGMII_TD4_R: R350.1 U4.34(TX_D4)
ETH2_RGMII_TD5_R: R351.1 U4.33(TX_D5)
ETH2_RGMII_TD6_R: R353.1 U4.32(TX_D6)
ETH2_RGMII_TD7_R: R352.1 U4.31(TX_D7)
ETH2_RGMII_TX_CTL: R362.1 R364.1 ; also on sheet 4
ETH2_RGMII_TX_CTL_R: R362.2 R363.2 U4.52(TX_EN/TX_CTRL)
ETH2_RGMII_TXC: R456.1 R457.1 ; also on sheet 4
ETH2_RGMII_TXC_R: R456.2 U4.40(GTX_CLK)
ETH_EARTH: C39.1 J3.SH3 R81.1 ; also on sheet 8
GPIO_ETH2/3_RESETn: R2.1 U2.1(A) ; also on sheet 4
PORz_OUT: U2.2(B) ; also on sheet 4 5
N16777232: J3.B12 R248.2
N16778463: Q21.1(G) R253.2
N16778486: Q17.1(G) R237.1
N16778543: Q15.1(G) R235.1
N16778588: FL3.2 J3.B9(VCC)
N16781731: J1.A12 R228.2
N16782941: Q11.1(G) R232.2
N16782964: Q7.1(G) R214.1
N16783021: Q5.1(G) R212.1
N16783066: FL1.2 J1.A9(VCC)
N17651014: TP18.1(TP) U9.17(VDDA1P8) U9.64(VDDA1P8)
N17652578: R111.1 U9.25(JTAG_CLK)
N17652582: R113.1 U9.27(JTAG_TMS)
N17653424: R107.2 U9.15(RBIAS)
N17654103: R112.1 U9.28(JTAG_TDI)
N17654395: R301.1 U9.24(JTAG_TRSTN)
N17656667: R314.1 U9.39(TX_ER)
N17658750: R326.1 R327.1 R446.1
N17658919: R335.1 R336.1 R338.1
N17659044: R345.1 R346.1 R447.1
N17664288: R48.2 U4.15(RBIAS)
N17665942: TP3.1(TP) U4.17(VDDA1P8) U4.64(VDDA1P8)
N17666876: R52.1 U4.25(JTAG_CLK)
N17666880: R54.1 U4.27(JTAG_TMS)
N17667185: R53.1 U4.28(JTAG_TDI)
N17667212: R349.1 U4.24(JTAG_TRSTN)
N17668919: R354.1 U4.39(TX_ER)
N17671387: R366.1 R367.1 R448.1
N17671564: R375.1 R376.1 R378.1
N17671685: R385.1 R387.1 R449.1

Not connected (* = marked no-connect by the designer): J1 SH1* SH2*; J3 SH4*; U4 1(RESERVED4)* 7(RESERVED3)* 9(RESERVED2)* 16(RESERVED1)* 18(X_O)* 26(JTAG_TDO)*; U9 1(RESERVED4)* 7(RESERVED3)* 9(RESERVED2)* 16(RESERVED1)* 18(X_O)* 26(JTAG_TDO)*

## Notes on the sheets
sheet 6
- STRAPPING RESISTORS
- RGMII Mode:
  Mount : R315, R316, R319, R321, R323,R454
  Unmount : R317, R318, R320, R322, R324, R338, R446, R447 ,R455
- MII Mode:
  Mount : R317, R318, R320, R322, R324, R338, R446, R447,R455
  Unmount : R315, R316, R319, R321, R323,R454
- PHY ADD = 00011
- Auto_neg =Enabled
  ANEGsel 10/100/1000
sheet 7
- STRAPPING RESISTORS
- RGMII Mode:
  Mount : R355, R357, R358, R360, R362,R456
  Unmount : R356, R359, R361, R363, R364, R378, R448, R449 ,R457
- MII Mode:
  Mount : R356, R359, R361, R363, R364, R378, R448, R449,R457
  Unmount : R355, R357, R358, R360, R362,R456
- PHY ADD = 00000
- Auto_neg =Enabled
  ANEGsel 10/100/1000
